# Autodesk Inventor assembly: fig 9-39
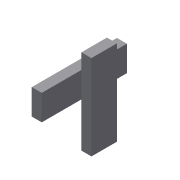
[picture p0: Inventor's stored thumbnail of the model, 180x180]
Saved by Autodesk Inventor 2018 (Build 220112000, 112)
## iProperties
Created: 2013-07
Part Number: fig 9-39
Document SubType Name: Assembly
Designer: CADCIM
Author: CADCIM
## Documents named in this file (2)
- E:\_Deepak\Inventor\Autodesk Inventor_2017_Project\Resources\Inventor_2018_Part\c09_Inv_2018\c09_inv_2018_prt\fig 9-39.iam
- E:\_Deepak\Inventor\Autodesk Inventor_2017_Project\Resources\Inventor_2018_Part\c09_Inv_2018\c09_inv_2018_prt\12.ipt
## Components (2 placed, 1 different names)
1. 12:1
2. 12:2
